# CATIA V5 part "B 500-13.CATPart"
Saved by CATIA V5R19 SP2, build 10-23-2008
Part number: B 500-13
Bounding box of the stored display mesh (mm): x -18.951 to 18.951, y -18.952 to 18.952, z 0 to 75.4
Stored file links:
  C:\Users\Bora\Desktop\3D Katı model\B serisi\B 500\B 500-13.CATPart
  C:\Program Files\Dassault Systemes\B19\intel_a\reffiles\standard\MetricThickPitch.txt
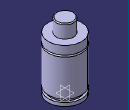
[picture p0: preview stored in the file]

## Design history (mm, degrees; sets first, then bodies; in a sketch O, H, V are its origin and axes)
Body1 (main body)
  Sketch1 on yz-plane, origin (0, 0, 0), H (0, 1, 0), V (0, 0, 1)
    point P1 (19, 50.9)
    point P4 (19, 48.9)
    point P7 (19, 50.9)
    point P8 (19, 48.9)
    point P9 (10, 74.4)
    point P11 (10, 74.4)
    line L1 (19, 50.9) -> (19, 60.4)
    line L2 (19, 7.5) -> (19, 48.9)
    line L3 (16.5, 7.5) -> (16.5, 4)
    arc A1 centre (19, 49.9) radius 1 from (19, 50.9) to (19, 48.9) ccw
    arc A2 centre (9, 74.4) radius 1 from (10, 74.4) to (9, 75.4) ccw
    line L4 (10, 74.4) -> (10, 60.4)
    line L5 (19, 0) -> (19, 4)
    line L6 (9, 75.4) -> (0, 75.4)
    point P15 (0, 75.4)
    line L7 (10, 60.4) -> (19, 60.4)
    line L8 (0, 0) -> (19, 0)
    line L9 (16.5, 7.5) -> (19, 7.5)
    line L10 (16.5, 4) -> (19, 4)
    coincidence: P15 V, P1 P7, P4 P8, P9 P11
    tangency: L6 A2
    horizontal: L7 H, L8 H, L9 H, L10 H
  Shaft1: profile Sketch1, axis Sketch1.V, angle 360
  Sketch2 on face of Shaft1 from Sketch1.L8, origin (0, 0, 0), H (1, 0, 0), V (0, -1, 0)
    point P1 (0, 0)
  Hole1: placed by Sketch2, at (0, 0, 0) direction (0, 0, 1), diameter 6.647, depth 7, threaded "M8", thread diameter 8, thread depth 7, pitch 1.25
